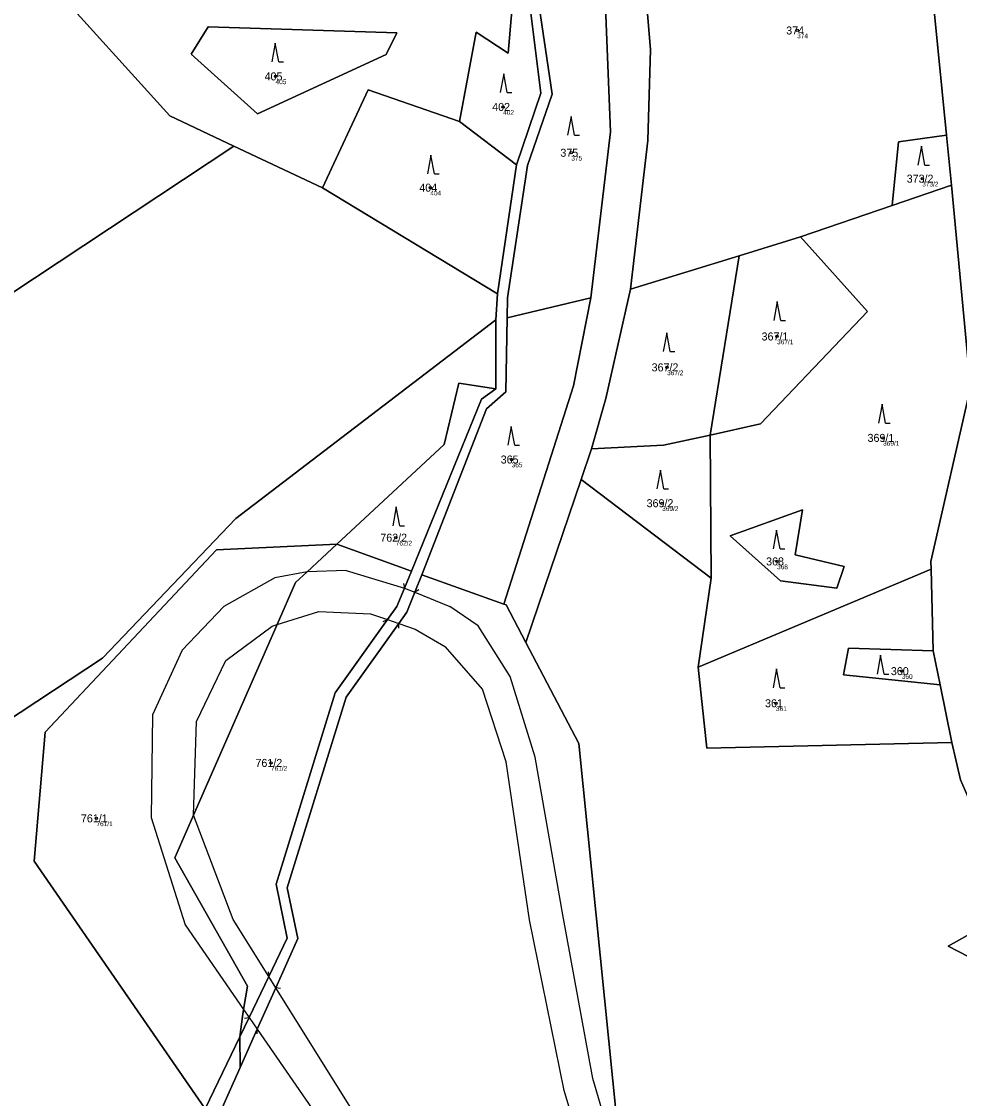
# Model space of a CAD drawing. Extents: x -554500 to -548272, y -1079733 to -1073730.
# Drawn here: x -551731.2 to -551532.1, y -1076321.4 to -1076092.7 of the extents above; entities that cross this region are included whole.
import ezdxf

# ---------------------------------------------------------------- set-up
doc = ezdxf.new("R2010")
doc.units = 0
for name, color, linetype in [('Definiční body', 7, 'Continuous'), ('Hranice parcel', 7, 'Continuous'), ('Parcelní čísla', 7, 'Continuous'), ('Polygon parcely', 7, 'Continuous'), ('Vnitřní kresba', 7, 'Continuous'), ('Značky kultur', 7, 'Continuous')]:
    doc.layers.add(name, color=color, linetype=linetype)

msp = doc.modelspace()

# ---------------------------------------------------------------- linework, layer by layer
at = {"layer": 'Definiční body'}
for centre in [(-551566.53, -1076094.62994), (-551677.29, -1076104.37994), (-551628.96, -1076110.85994), (-551614.49, -1076120.58994), (-551539.98, -1076126.08994), (-551644.43, -1076127.99994), (-551570.79, -1076159.59994), (-551594.14, -1076166.15994), (-551548.29, -1076181.12994), (-551627.16, -1076185.71994), (-551595.2, -1076194.99994), (-551651.75, -1076202.31994), (-551570.8, -1076207.35994), (-551544.31, -1076230.64994), (-551571.03, -1076237.46994), (-551678.26, -1076250.13994), (-551715.32, -1076261.90994)]:
    msp.add_circle(centre, 0.25, dxfattribs=at)
at = {"layer": 'Hranice parcel'}
for p, q in [((-551534.79, -1076116.85), (-551542.24, -1076041.93)), ((-551638.24, -1076113.94), (-551626.14, -1076123.19)), ((-551533.73, -1076127.47), (-551534.79, -1076116.85)), ((-551686.16, -1076119.16), (-551667.32, -1076128.02)), ((-551630.15, -1076150.54), (-551626.14, -1076123.19)), ((-551667.32, -1076128.02), (-551630.15, -1076150.54)), ((-551533.73, -1076127.47), (-551546.38, -1076131.81)), ((-551546.38, -1076131.81), (-551565.81, -1076138.47)), ((-551565.81, -1076138.47), (-551578.88, -1076142.47)), ((-551578.88, -1076142.47), (-551601.95, -1076149.57)), ((-551578.88, -1076142.47), (-551585.03, -1076180.52)), ((-551630.53, -1076156.04), (-551630.15, -1076150.54)), ((-551610.31, -1076151.41), (-551628.11, -1076155.63)), ((-551630.53, -1076156.04), (-551630.5, -1076170.74)), ((-551585.03, -1076180.52), (-551584.8, -1076210.89)), ((-551610.17, -1076183.44), (-551612.39, -1076189.95)), ((-551612.39, -1076189.95), (-551624.17, -1076224.55)), ((-551584.8, -1076210.89), (-551612.39, -1076189.95)), ((-551648.43, -1076209.4), (-551664.29, -1076203.7)), ((-551646.24, -1076210.19), (-551628.84, -1076216.43)), ((-551538.1, -1076208.98), (-551587.53, -1076229.8)), ((-551537.62, -1076226.33), (-551538.1, -1076208.98)), ((-551587.53, -1076229.8), (-551584.8, -1076210.89)), ((-551536.16, -1076233.53), (-551537.62, -1076226.33)), ((-551533.67, -1076245.78), (-551536.16, -1076233.53)), ((-551684.89, -1076308.33), (-551692.21, -1076323.59)), ((-551684.81, -1076314.8), (-551684.89, -1076308.33)), ((-551684.81, -1076314.8), (-551690.07, -1076326.58))]:
    msp.add_line(p, q, dxfattribs=at)
for points in [[(-551626.14, -1076123.19), (-551620.93, -1076107.93), (-551623.91, -1076084.12), (-551620.48, -1076059.64)], [(-551600.98, -1076058.92), (-551597.7, -1076098.66), (-551598.21, -1076117.99), (-551601.95, -1076149.57)], [(-551624.59, -1076060.94), (-551627.88, -1076099.47), (-551634.72, -1076095.02), (-551638.24, -1076113.94)], [(-551756.29, -1076076.9), (-551726.14, -1076083.51), (-551699.72, -1076112.72), (-551686.16, -1076119.16)], [(-551620.39, -1076077.11), (-551621.91, -1076085.63), (-551618.58, -1076108.12), (-551623.81, -1076123.27), (-551628.05, -1076151.37), (-551628.11, -1076155.63)], [(-551610.31, -1076151.41), (-551606.16, -1076116.16), (-551607.32, -1076087.79)], [(-551651.55, -1076095.11), (-551691.58, -1076093.88), (-551695.2, -1076099.67), (-551681.15, -1076112.3), (-551653.79, -1076099.7), (-551651.55, -1076095.11)], [(-551638.24, -1076113.94), (-551657.64, -1076107.23), (-551667.32, -1076128.02)], [(-551534.79, -1076116.85), (-551544.99, -1076118.29), (-551546.38, -1076131.81)], [(-551792.57, -1076198.75), (-551786.77, -1076185.81), (-551686.16, -1076119.16)], [(-551538.1, -1076208.98), (-551538.14, -1076207.35), (-551529.71, -1076170.45), (-551533.73, -1076127.47)], [(-551585.03, -1076180.52), (-551574.29, -1076178.18), (-551551.62, -1076154.27), (-551565.81, -1076138.47)], [(-551601.95, -1076149.57), (-551607.13, -1076172.8), (-551610.17, -1076183.44)], [(-551628.84, -1076216.43), (-551614.01, -1076170.1), (-551610.31, -1076151.41)], [(-551628.11, -1076155.63), (-551628.39, -1076171.37), (-551632.48, -1076174.99), (-551646.24, -1076210.19)], [(-551747.74, -1076255.1), (-551741.99, -1076246.33), (-551714.04, -1076227.92), (-551685.71, -1076198.28), (-551630.53, -1076156.04)], [(-551664.29, -1076203.7), (-551641.46, -1076182.55), (-551638.36, -1076169.52), (-551630.5, -1076170.74)], [(-551630.5, -1076170.74), (-551633.58, -1076172.91), (-551648.43, -1076209.4)], [(-551610.17, -1076183.44), (-551594.88, -1076182.66), (-551585.03, -1076180.52)], [(-551565.43, -1076196.37), (-551580.74, -1076201.92), (-551570.05, -1076211.5), (-551558.11, -1076213.02), (-551556.53, -1076208.42), (-551566.95, -1076205.96), (-551565.43, -1076196.37)], [(-551664.29, -1076203.7), (-551689.85, -1076204.91), (-551726.2, -1076243.62), (-551728.52, -1076271.01), (-551692.21, -1076323.59)], [(-551684.89, -1076308.33), (-551684.3, -1076303.95), (-551684.06, -1076302.5), (-551683.24, -1076297.51), (-551698.68, -1076270.27), (-551694.7, -1076261.2), (-551676.97, -1076220.75), (-551673.06, -1076211.84), (-551670.59, -1076209.6), (-551664.29, -1076203.7)], [(-551648.43, -1076209.4), (-551649.91, -1076213.02), (-551651.51, -1076216.95), (-551653.5, -1076219.72), (-551664.63, -1076235.23), (-551677.13, -1076275.85), (-551674.81, -1076287.33), (-551678.72, -1076295.48), (-551682.9, -1076304.18), (-551684.89, -1076308.33)], [(-551646.24, -1076210.19), (-551647.73, -1076213.91), (-551649.39, -1076218.1), (-551651.13, -1076220.54), (-551662.28, -1076236.16), (-551674.85, -1076276.68), (-551672.58, -1076287.44), (-551677.24, -1076297.86), (-551681.18, -1076306.67), (-551684.81, -1076314.8)], [(-551628.84, -1076216.43), (-551628.35, -1076216.61), (-551624.17, -1076224.55)], [(-551624.17, -1076224.55), (-551612.88, -1076245.99), (-551603.81, -1076335.92)], [(-551537.62, -1076226.33), (-551555.6, -1076225.8), (-551556.66, -1076231.47), (-551536.16, -1076233.53)], [(-551533.67, -1076245.78), (-551585.71, -1076247.01), (-551587.53, -1076229.8)], [(-551519.94, -1076280.94), (-551531.84, -1076253.73), (-551533.67, -1076245.78)], [(-551516.66, -1076291.98), (-551523.79, -1076294.55), (-551534.46, -1076289.08), (-551519.94, -1076280.94)]]:
    msp.add_lwpolyline(points, dxfattribs=at)
at = {"layer": 'Polygon parcely'}
for points in [[(-551564.05, -1075824.19), (-551560.75, -1075872.41), (-551549.96, -1075966.9), (-551542.24, -1076041.93), (-551534.79, -1076116.85), (-551533.73, -1076127.47), (-551529.71, -1076170.45), (-551538.14, -1076207.35), (-551538.1, -1076208.98), (-551537.62, -1076226.33), (-551536.16, -1076233.53), (-551533.67, -1076245.78), (-551531.84, -1076253.73), (-551519.94, -1076280.94), (-551516.66, -1076291.98), (-551510.06, -1076315.85), (-551514.11, -1076329.03)], [(-551607.32, -1076087.79), (-551606.16, -1076116.16), (-551610.31, -1076151.41), (-551614.01, -1076170.1), (-551628.84, -1076216.43), (-551628.35, -1076216.61), (-551624.17, -1076224.55), (-551612.39, -1076189.95), (-551610.17, -1076183.44), (-551607.13, -1076172.8), (-551601.95, -1076149.57), (-551598.21, -1076117.99), (-551597.7, -1076098.66), (-551600.98, -1076058.92)], [(-551623.91, -1076084.12), (-551620.93, -1076107.93), (-551626.14, -1076123.19), (-551630.15, -1076150.54), (-551630.53, -1076156.04), (-551630.5, -1076170.74), (-551633.58, -1076172.91), (-551648.43, -1076209.4), (-551649.91, -1076213.02), (-551651.51, -1076216.95), (-551653.5, -1076219.72), (-551664.63, -1076235.23), (-551677.13, -1076275.85), (-551674.81, -1076287.33), (-551678.72, -1076295.48), (-551682.9, -1076304.18), (-551684.89, -1076308.33), (-551684.81, -1076314.8), (-551681.18, -1076306.67), (-551677.24, -1076297.86), (-551672.58, -1076287.44), (-551674.85, -1076276.68), (-551662.28, -1076236.16), (-551651.13, -1076220.54), (-551649.39, -1076218.1), (-551647.73, -1076213.91), (-551646.24, -1076210.19), (-551632.48, -1076174.99), (-551628.39, -1076171.37), (-551628.11, -1076155.63), (-551628.05, -1076151.37), (-551623.81, -1076123.27), (-551618.58, -1076108.12), (-551621.91, -1076085.63)], [(-551692.21, -1076323.59), (-551728.52, -1076271.01), (-551726.2, -1076243.62), (-551689.85, -1076204.91), (-551664.29, -1076203.7), (-551641.46, -1076182.55), (-551638.36, -1076169.52), (-551630.5, -1076170.74), (-551630.53, -1076156.04), (-551685.71, -1076198.28), (-551714.04, -1076227.92), (-551741.99, -1076246.33), (-551747.74, -1076255.1), (-551769.28, -1076287.95), (-551781.19, -1076294.28), (-551802.09, -1076297.51), (-551831.23, -1076291.57), (-551816.28, -1076313.27), (-551800.16, -1076324.48)], [(-551514.11, -1076329.03), (-551510.06, -1076315.85), (-551516.66, -1076291.98), (-551523.79, -1076294.55), (-551534.46, -1076289.08), (-551519.94, -1076280.94), (-551531.84, -1076253.73), (-551533.67, -1076245.78), (-551585.71, -1076247.01), (-551587.53, -1076229.8), (-551584.8, -1076210.89), (-551612.39, -1076189.95), (-551624.17, -1076224.55), (-551612.88, -1076245.99), (-551603.81, -1076335.92)], [(-551603.81, -1076335.92), (-551612.88, -1076245.99), (-551624.17, -1076224.55), (-551628.35, -1076216.61), (-551628.84, -1076216.43), (-551646.24, -1076210.19), (-551647.73, -1076213.91), (-551649.39, -1076218.1), (-551651.13, -1076220.54), (-551662.28, -1076236.16), (-551674.85, -1076276.68), (-551672.58, -1076287.44), (-551677.24, -1076297.86), (-551681.18, -1076306.67), (-551684.81, -1076314.8), (-551690.07, -1076326.58)]]:
    msp.add_lwpolyline(points, dxfattribs=at)
for points in [[(-551561.93, -1076048.52), (-551583.19, -1076054.67), (-551600.98, -1076058.92), (-551597.7, -1076098.66), (-551598.21, -1076117.99), (-551601.95, -1076149.57), (-551578.88, -1076142.47), (-551565.81, -1076138.47), (-551546.38, -1076131.81), (-551544.99, -1076118.29), (-551534.79, -1076116.85), (-551542.24, -1076041.93)], [(-551726.14, -1076083.51), (-551699.72, -1076112.72), (-551686.16, -1076119.16), (-551667.32, -1076128.02), (-551657.64, -1076107.23), (-551638.24, -1076113.94), (-551634.72, -1076095.02), (-551627.88, -1076099.47), (-551624.59, -1076060.94), (-551639.56, -1076065.66), (-551635.43, -1076066.01), (-551635.82, -1076073.81), (-551664.23, -1076072.59), (-551684.78, -1076065.17), (-551734.71, -1076049.71), (-551754.22, -1076069.17), (-551756.29, -1076076.9)], [(-551638.24, -1076113.94), (-551626.14, -1076123.19), (-551620.93, -1076107.93), (-551623.91, -1076084.12), (-551620.48, -1076059.64), (-551624.59, -1076060.94), (-551627.88, -1076099.47), (-551634.72, -1076095.02)], [(-551827.32, -1076202.72), (-551792.57, -1076198.75), (-551786.77, -1076185.81), (-551686.16, -1076119.16), (-551699.72, -1076112.72), (-551726.14, -1076083.51), (-551756.29, -1076076.9), (-551767.61, -1076074.74), (-551781.6, -1076074.58), (-551852.25, -1076122.68), (-551984.49, -1076130.66), (-552029.02, -1076134.09), (-551935.03, -1076207.31), (-551915.13, -1076206.62), (-551866.58, -1076199.98)], [(-551621.91, -1076085.63), (-551618.58, -1076108.12), (-551623.81, -1076123.27), (-551628.05, -1076151.37), (-551628.11, -1076155.63), (-551610.31, -1076151.41), (-551606.16, -1076116.16), (-551607.32, -1076087.79), (-551615.69, -1076087.6), (-551620.39, -1076077.11)], [(-551651.55, -1076095.11), (-551653.79, -1076099.7), (-551681.15, -1076112.3), (-551695.2, -1076099.67), (-551691.58, -1076093.88)], [(-551651.55, -1076095.11), (-551691.58, -1076093.88), (-551695.2, -1076099.67), (-551681.15, -1076112.3), (-551653.79, -1076099.7)], [(-551626.14, -1076123.19), (-551638.24, -1076113.94), (-551657.64, -1076107.23), (-551667.32, -1076128.02), (-551630.15, -1076150.54)], [(-551546.38, -1076131.81), (-551533.73, -1076127.47), (-551534.79, -1076116.85), (-551544.99, -1076118.29)], [(-551714.04, -1076227.92), (-551685.71, -1076198.28), (-551630.53, -1076156.04), (-551630.15, -1076150.54), (-551667.32, -1076128.02), (-551686.16, -1076119.16), (-551786.77, -1076185.81), (-551792.57, -1076198.75), (-551794.66, -1076203.4), (-551801.28, -1076218.16), (-551814.44, -1076226.53), (-551828.15, -1076227.75), (-551829.36, -1076273.27), (-551784.29, -1076273.29), (-551765.01, -1076245.99), (-551747.74, -1076255.1), (-551741.99, -1076246.33)], [(-551546.38, -1076131.81), (-551565.81, -1076138.47), (-551551.62, -1076154.27), (-551574.29, -1076178.18), (-551585.03, -1076180.52), (-551584.8, -1076210.89), (-551587.53, -1076229.8), (-551538.1, -1076208.98), (-551538.14, -1076207.35), (-551529.71, -1076170.45), (-551533.73, -1076127.47)], [(-551574.29, -1076178.18), (-551551.62, -1076154.27), (-551565.81, -1076138.47), (-551578.88, -1076142.47), (-551585.03, -1076180.52)], [(-551610.17, -1076183.44), (-551594.88, -1076182.66), (-551585.03, -1076180.52), (-551578.88, -1076142.47), (-551601.95, -1076149.57), (-551607.13, -1076172.8)], [(-551628.39, -1076171.37), (-551632.48, -1076174.99), (-551646.24, -1076210.19), (-551628.84, -1076216.43), (-551614.01, -1076170.1), (-551610.31, -1076151.41), (-551628.11, -1076155.63)], [(-551648.43, -1076209.4), (-551633.58, -1076172.91), (-551630.5, -1076170.74), (-551638.36, -1076169.52), (-551641.46, -1076182.55), (-551664.29, -1076203.7)], [(-551612.39, -1076189.95), (-551584.8, -1076210.89), (-551585.03, -1076180.52), (-551594.88, -1076182.66), (-551610.17, -1076183.44)], [(-551565.43, -1076196.37), (-551580.74, -1076201.92), (-551570.05, -1076211.5), (-551558.11, -1076213.02), (-551556.53, -1076208.42), (-551566.95, -1076205.96)], [(-551565.43, -1076196.37), (-551566.95, -1076205.96), (-551556.53, -1076208.42), (-551558.11, -1076213.02), (-551570.05, -1076211.5), (-551580.74, -1076201.92)], [(-551728.52, -1076271.01), (-551692.21, -1076323.59), (-551684.89, -1076308.33), (-551684.3, -1076303.95), (-551684.06, -1076302.5), (-551683.24, -1076297.51), (-551698.68, -1076270.27), (-551694.7, -1076261.2), (-551676.97, -1076220.75), (-551673.06, -1076211.84), (-551670.59, -1076209.6), (-551664.29, -1076203.7), (-551689.85, -1076204.91), (-551726.2, -1076243.62)], [(-551648.43, -1076209.4), (-551664.29, -1076203.7), (-551670.59, -1076209.6), (-551673.06, -1076211.84), (-551676.97, -1076220.75), (-551694.7, -1076261.2), (-551698.68, -1076270.27), (-551683.24, -1076297.51), (-551684.06, -1076302.5), (-551684.3, -1076303.95), (-551684.89, -1076308.33), (-551682.9, -1076304.18), (-551678.72, -1076295.48), (-551674.81, -1076287.33), (-551677.13, -1076275.85), (-551664.63, -1076235.23), (-551653.5, -1076219.72), (-551651.51, -1076216.95), (-551649.91, -1076213.02)], [(-551538.1, -1076208.98), (-551587.53, -1076229.8), (-551585.71, -1076247.01), (-551533.67, -1076245.78), (-551536.16, -1076233.53), (-551556.66, -1076231.47), (-551555.6, -1076225.8), (-551537.62, -1076226.33)], [(-551555.6, -1076225.8), (-551556.66, -1076231.47), (-551536.16, -1076233.53), (-551537.62, -1076226.33)], [(-551519.94, -1076280.94), (-551534.46, -1076289.08), (-551523.79, -1076294.55), (-551516.66, -1076291.98)], [(-551684.81, -1076314.8), (-551684.89, -1076308.33), (-551692.21, -1076323.59), (-551693.84, -1076326.98), (-551691.26, -1076331.97), (-551680.51, -1076352.78), (-551679.34, -1076349.74), (-551690.07, -1076326.58)]]:
    msp.add_lwpolyline(points, close=True, dxfattribs=at)
at = {"layer": 'Vnitřní kresba'}
for p, q in [((-551670.59, -1076209.6), (-551677.41, -1076210.84)), ((-551662.28, -1076209.27), (-551670.59, -1076209.6)), ((-551662.28, -1076209.27), (-551649.91, -1076213.02)), ((-551677.41, -1076210.84), (-551688.28, -1076216.95)), ((-551650.117, -1076212.041), (-551649.91, -1076213.019)), ((-551649.91, -1076213.02), (-551647.73, -1076213.91)), ((-551647.73, -1076213.91), (-551640.31, -1076216.92)), ((-551646.863, -1076213.41), (-551647.729, -1076213.91)), ((-551688.28, -1076216.95), (-551697.11, -1076226.23)), ((-551634.3, -1076221.06), (-551640.31, -1076216.92)), ((-551676.97, -1076220.75), (-551668.08, -1076217.99)), ((-551668.08, -1076217.99), (-551657.1, -1076218.47)), ((-551657.1, -1076218.47), (-551653.5, -1076219.72)), ((-551654.407, -1076220.142), (-551653.501, -1076219.72)), ((-551653.5, -1076219.72), (-551651.13, -1076220.54)), ((-551687.82, -1076228.4), (-551677.99, -1076221.07)), ((-551677.99, -1076221.07), (-551676.97, -1076220.75)), ((-551651.131, -1076221.54), (-551651.131, -1076220.541)), ((-551651.13, -1076220.54), (-551647.65, -1076221.75)), ((-551647.65, -1076221.75), (-551641.2, -1076225.51)), ((-551627.47, -1076231.81), (-551634.3, -1076221.06)), ((-551697.11, -1076226.23), (-551703.42, -1076239.92)), ((-551633.32, -1076234.49), (-551641.2, -1076225.51)), ((-551694.08, -1076241.38), (-551687.82, -1076228.4)), ((-551622.19, -1076248.9), (-551627.47, -1076231.81)), ((-551628.31, -1076249.92), (-551633.32, -1076234.49)), ((-551703.42, -1076239.92), (-551703.73, -1076261.76)), ((-551694.7, -1076261.2), (-551694.08, -1076241.38)), ((-551616.26, -1076282.41), (-551622.19, -1076248.9)), ((-551623.39, -1076283.47), (-551628.31, -1076249.92)), ((-551703.73, -1076261.76), (-551696.45, -1076284.55)), ((-551686.28, -1076283.38), (-551694.7, -1076261.2)), ((-551678.72, -1076295.48), (-551686.28, -1076283.38)), ((-551616.02, -1076319.67), (-551623.39, -1076283.47)), ((-551609.9, -1076317.12), (-551616.26, -1076282.41)), ((-551696.45, -1076284.55), (-551684.06, -1076302.5)), ((-551678.824, -1076294.485), (-551678.719, -1076295.479)), ((-551677.24, -1076297.86), (-551678.72, -1076295.48)), ((-551654.6, -1076334.11), (-551677.24, -1076297.86)), ((-551676.258, -1076298.051), (-551677.24, -1076297.861)), ((-551684.06, -1076302.5), (-551682.9, -1076304.18)), ((-551683.888, -1076304.336), (-551682.901, -1076304.18)), ((-551682.9, -1076304.18), (-551681.18, -1076306.67)), ((-551681.198, -1076307.67), (-551681.181, -1076306.671)), ((-551681.18, -1076306.67), (-551659.98, -1076337.36)), ((-551604.24, -1076336.42), (-551609.9, -1076317.12)), ((-551610.02, -1076339.31), (-551616.02, -1076319.67))]:
    msp.add_line(p, q, dxfattribs=at)
at = {"layer": 'Značky kultur'}
for p, q in [((-551677.34, -1076097.29), (-551678.09, -1076101.29)), ((-551676.59, -1076101.29), (-551677.34, -1076097.29)), ((-551676.59, -1076101.29), (-551675.594, -1076101.29)), ((-551628.83, -1076103.81), (-551629.58, -1076107.81)), ((-551628.08, -1076107.81), (-551628.83, -1076103.81)), ((-551628.08, -1076107.81), (-551627.084, -1076107.81)), ((-551614.53, -1076112.88), (-551615.28, -1076116.88)), ((-551613.78, -1076116.88), (-551614.53, -1076112.88)), ((-551613.78, -1076116.88), (-551612.784, -1076116.88)), ((-551540.16, -1076119.21), (-551540.91, -1076123.21)), ((-551539.41, -1076123.21), (-551540.16, -1076119.21)), ((-551644.31, -1076121.08), (-551645.06, -1076125.08)), ((-551643.56, -1076125.08), (-551644.31, -1076121.08)), ((-551539.41, -1076123.21), (-551538.414, -1076123.21)), ((-551643.56, -1076125.08), (-551642.564, -1076125.08)), ((-551570.77, -1076152.19), (-551571.52, -1076156.19)), ((-551570.02, -1076156.19), (-551570.77, -1076152.19)), ((-551570.02, -1076156.19), (-551569.024, -1076156.19)), ((-551594.22, -1076158.79), (-551594.97, -1076162.79)), ((-551593.47, -1076162.79), (-551594.22, -1076158.79)), ((-551593.47, -1076162.79), (-551592.474, -1076162.79)), ((-551548.5, -1076173.99), (-551549.25, -1076177.99)), ((-551547.75, -1076177.99), (-551548.5, -1076173.99)), ((-551627.23, -1076178.7), (-551627.98, -1076182.7)), ((-551626.48, -1076182.7), (-551627.23, -1076178.7)), ((-551547.75, -1076177.99), (-551546.754, -1076177.99)), ((-551626.48, -1076182.7), (-551625.484, -1076182.7)), ((-551595.58, -1076187.97), (-551596.33, -1076191.97)), ((-551594.83, -1076191.97), (-551595.58, -1076187.97)), ((-551594.83, -1076191.97), (-551593.834, -1076191.97)), ((-551651.67, -1076195.78), (-551652.42, -1076199.78)), ((-551650.92, -1076199.78), (-551651.67, -1076195.78)), ((-551650.92, -1076199.78), (-551649.924, -1076199.78)), ((-551570.91, -1076200.69), (-551571.66, -1076204.69)), ((-551570.16, -1076204.69), (-551570.91, -1076200.69)), ((-551570.16, -1076204.69), (-551569.164, -1076204.69)), ((-551548.82, -1076227.28), (-551549.57, -1076231.28)), ((-551548.07, -1076231.28), (-551548.82, -1076227.28)), ((-551570.9, -1076230.17), (-551571.65, -1076234.17)), ((-551570.15, -1076234.17), (-551570.9, -1076230.17)), ((-551548.07, -1076231.28), (-551547.074, -1076231.28)), ((-551570.15, -1076234.17), (-551569.154, -1076234.17))]:
    msp.add_line(p, q, dxfattribs=at)

# ---------------------------------------------------------------- texts
at = {"layer": 'Definiční body'}
for s, p in [('374', (-551566.53, -1076096.286)), ('405', (-551677.29, -1076106.036)), ('402', (-551628.96, -1076112.516)), ('375', (-551614.49, -1076122.246)), ('373/2', (-551539.98, -1076127.746)), ('404', (-551644.43, -1076129.656)), ('367/1', (-551570.79, -1076161.256)), ('367/2', (-551594.14, -1076167.816)), ('369/1', (-551548.29, -1076182.786)), ('365', (-551627.16, -1076187.376)), ('369/2', (-551595.2, -1076196.656)), ('762/2', (-551651.75, -1076203.976)), ('368', (-551570.8, -1076209.016)), ('360', (-551544.31, -1076232.306)), ('361', (-551571.03, -1076239.126)), ('761/2', (-551678.26, -1076251.796)), ('761/1', (-551715.32, -1076263.566))]:
    msp.add_text(s, height=0.999996, dxfattribs=at).set_placement(p)
at = {"layer": 'Parcelní čísla'}
for s, p in [('374', (-551568.855, -1076095.48)), ('405', (-551679.615, -1076105.23)), ('402', (-551631.285, -1076111.71)), ('375', (-551616.815, -1076121.44)), ('373/2', (-551543.278, -1076126.94)), ('404', (-551646.755, -1076128.85)), ('367/1', (-551574.088, -1076160.45)), ('367/2', (-551597.438, -1076167.01)), ('369/1', (-551551.588, -1076181.98)), ('365', (-551629.485, -1076186.57)), ('369/2', (-551598.498, -1076195.85)), ('762/2', (-551655.048, -1076203.17)), ('368', (-551573.125, -1076208.21)), ('360', (-551546.635, -1076231.5)), ('361', (-551573.355, -1076238.32)), ('761/2', (-551681.558, -1076250.99)), ('761/1', (-551718.618, -1076262.76))]:
    msp.add_text(s, height=1.699998, dxfattribs=at).set_placement(p)

doc.saveas('drawing.dxf')
